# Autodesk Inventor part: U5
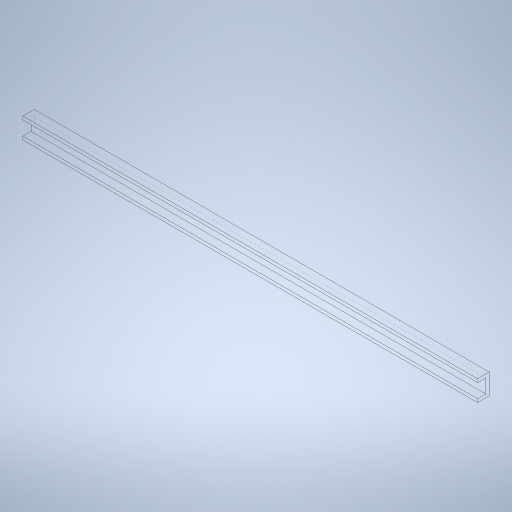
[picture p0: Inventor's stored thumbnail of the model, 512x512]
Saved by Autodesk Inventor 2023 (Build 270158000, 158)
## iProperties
Created: 2023-11
Part Number: U5
Material: Generic
Document SubType Name: Modeling
Designer: tornqvih
Density: 1 g/cm^3
Appearance: Default
Author: tornqvih
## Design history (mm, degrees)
sketch "Sketch1"
  geometry: L1 (6.25, 2.5)-(6.25, -4.5); L2 (6.25, -4.5)-(-6.25, -4.5); L3 (-6.25, -4.5)-(-6.25, 2.5); L4 (-6.25, 2.5)-(-4.25, 2.5); L5 (-4.25, 2.5)-(-4.25, -2.5); L6 (-4.25, -2.5)-(4.25, -2.5); L7 (4.25, -2.5)-(4.25, 2.5); L8 (4.25, 2.5)-(6.25, 2.5); L9 (0, -5.9)-(0, 3.9) reference; L10 (-8.75, 0)-(8.75, 0) reference; 1 further point
  constraints: 16 end point, 5 symmetric about line, 2 vertical, 1 horizontal alignment, 1 point on line
  dimensions: "d0" = 5 distance of L6.end L7.end; "d1" = 2 distance between parallel lines of L1 L7; "d2" = 2 distance between parallel lines of L2 L6; "d3" = 8.5 distance of L5.end L6.end
extrude "Extrusion1" new body sketch "Sketch1" distance "d4" = 275; taper "d5" = 0 deg
body "Solid1"
